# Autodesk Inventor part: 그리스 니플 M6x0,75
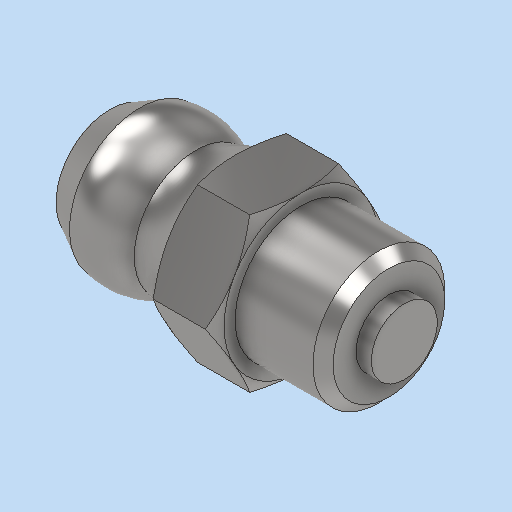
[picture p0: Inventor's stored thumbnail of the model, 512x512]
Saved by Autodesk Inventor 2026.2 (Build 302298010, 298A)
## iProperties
Created: 2026-03
Part Number: 그리스 니플 M6x0,75
Material: 강철, 연강
Description: 윤활 니플, 원추 유형 A
Document SubType Name: Modeling
Designer: PC-2-06
Density: 7.85 g/cm^3
Appearance: 기본값
Author: jhkim
Sending System: Autodesk Inventor 2026
Preprocessor: ST-DEVELOPER v20.1
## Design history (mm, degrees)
feature "Solid1"
node "솔리드1"
